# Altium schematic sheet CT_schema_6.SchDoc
size 245 x 144 mm
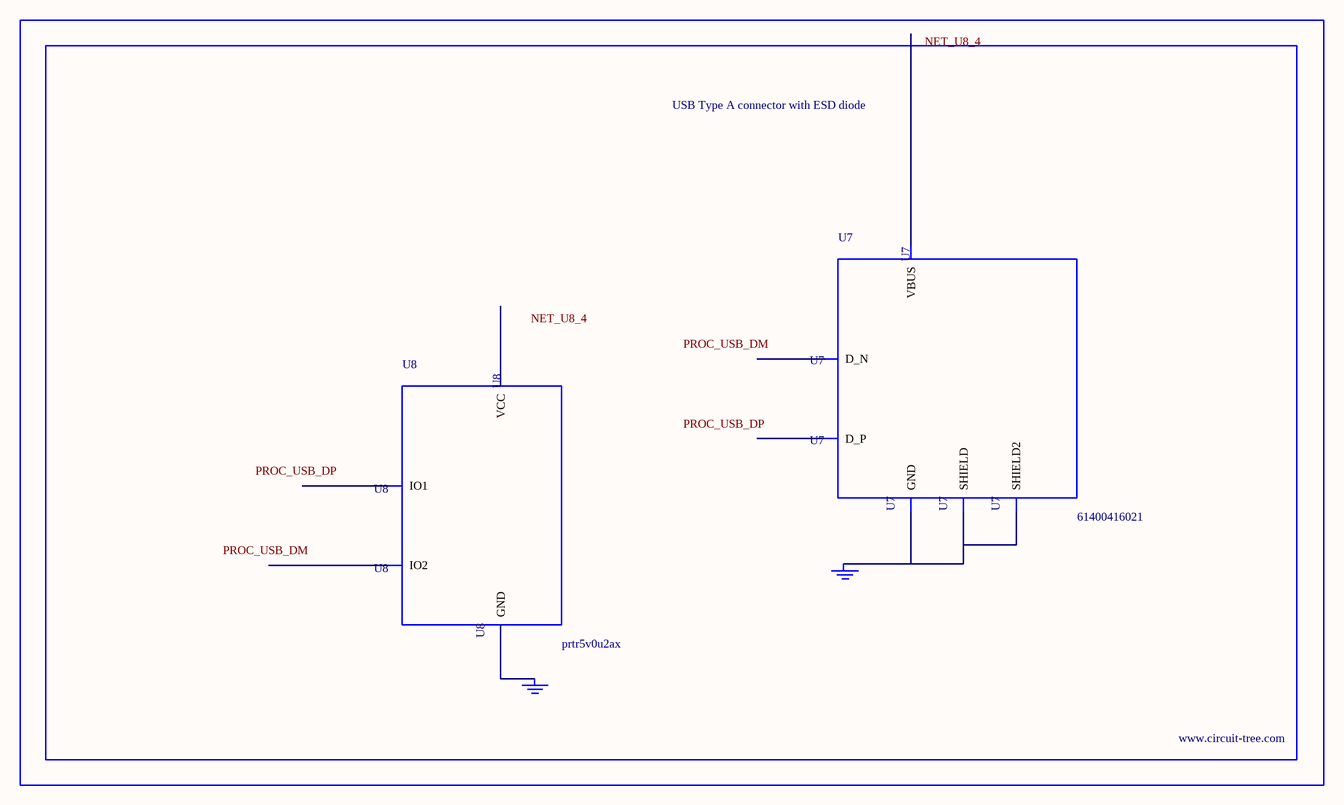
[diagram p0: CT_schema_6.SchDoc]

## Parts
BORDER5  (no value)
GND_INSTANCE_5_0  (no value)
GND_INSTANCE_5_1  (no value)
U7  61400416021  [USB-A-H]
U8  prtr5v0u2ax  [SOT143B]

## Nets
NetGND_INSTANCE_5_0_0: GND_INSTANCE_5_0.0(GND) U7.4(GND) U7.5(SHIELD) U7.6(SHIELD2)
NetGND_INSTANCE_5_1_0: GND_INSTANCE_5_1.0(GND) U8.1(GND)

Not connected (* = marked no-connect by the designer): U7 1(VBUS) 2(D_N) 3(D_P); U8 2(IO1) 3(IO2) 4(VCC)

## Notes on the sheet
- Labels drawn without touching a wire or pin: NET_U8_4, PROC_USB_DM, PROC_USB_DP

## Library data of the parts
BORDER5 = BORDER_PAGE5
GND_INSTANCE_5_0 GND_INSTANCE_5_1 = GND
